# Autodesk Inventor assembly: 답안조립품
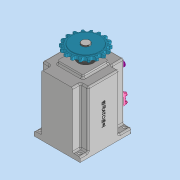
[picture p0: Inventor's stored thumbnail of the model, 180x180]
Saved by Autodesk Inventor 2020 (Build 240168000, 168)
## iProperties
Created: 2022-01
Part Number: 답안조립품
Document SubType Name: Assembly
Designer: user
Author: user
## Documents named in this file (16)
- C:\Users\user\Desktop\720112V1008\답안조립품.iam
- C:\Users\user\Desktop\720112V1008\멈춤나사 M3.ipt
- C:\Users\user\Desktop\720112V1008\메인 축.ipt
- C:\Users\user\Desktop\720112V1008\베어링 608.ipt
- C:\Users\user\Desktop\720112V1008\베어링 6003.ipt
- C:\Users\user\Desktop\720112V1008\본체.ipt
- C:\Users\user\Desktop\720112V1008\볼트 M4 x 10.ipt
- C:\Users\user\Desktop\720112V1008\부시.ipt
- C:\Users\user\Desktop\720112V1008\상부 캡.ipt
- C:\Users\user\Desktop\720112V1008\서브 축.ipt
- C:\Users\user\Desktop\720112V1008\스프로킷.ipt
- C:\Users\user\Desktop\720112V1008\슬라이더.ipt
- C:\Users\user\Desktop\720112V1008\오일 실 8 x 22 x 7.ipt
- C:\Users\user\Desktop\720112V1008\오일 실 17 x 32 x 8.ipt
- C:\Users\user\Desktop\720112V1008\커버.ipt
- C:\Users\user\Desktop\720112V1008\키 5 x 5.ipt
